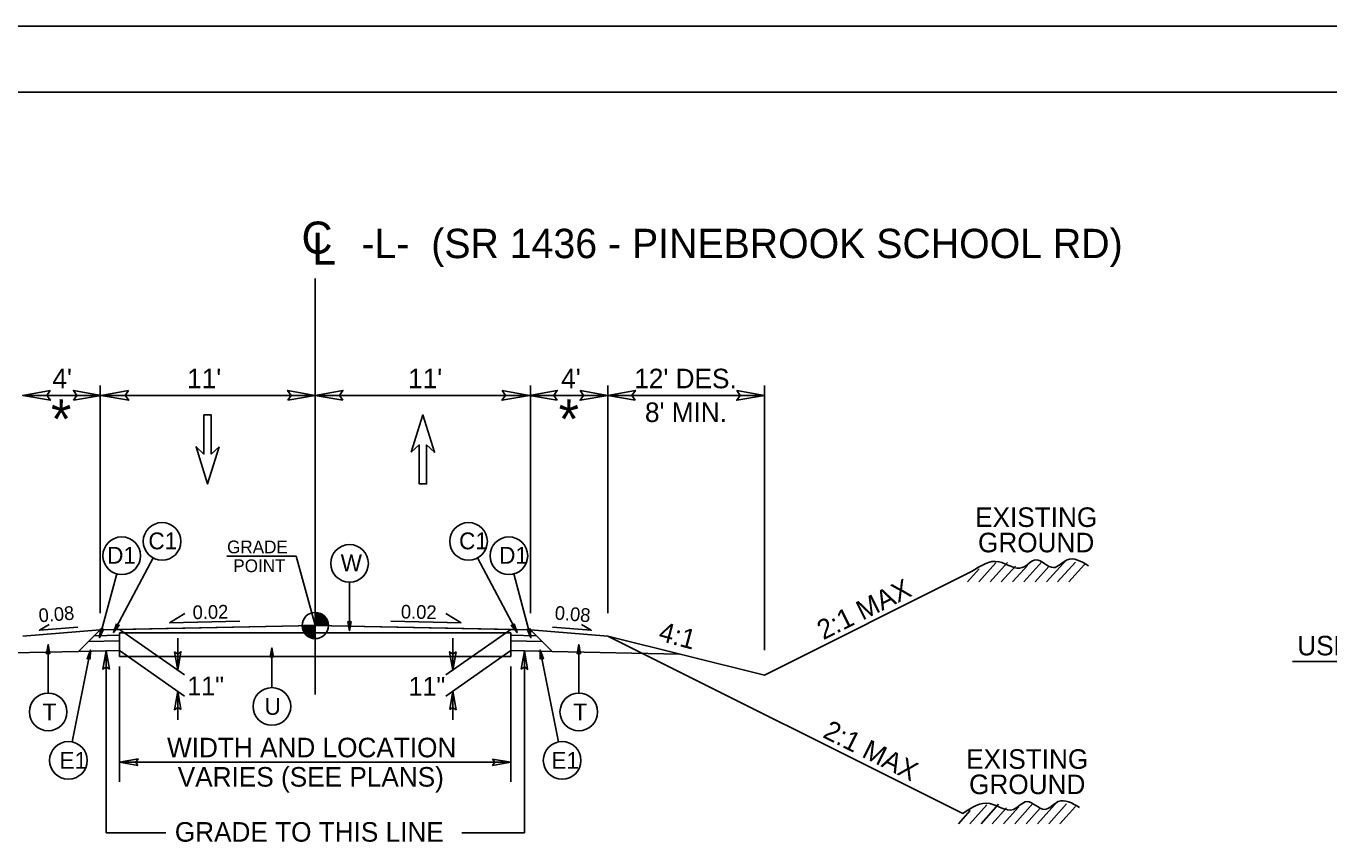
# Model space of a CAD drawing. Extents: x 1553884 to 1554215, y 810431 to 810779.
# Drawn here: x 1553946.8 to 1554013.4, y 810737.7 to 810779.4 of the extents above; entities that cross this region are included whole.
import ezdxf

# ---------------------------------------------------------------- set-up
doc = ezdxf.new("R2010")
doc.units = 0
for name, color, linetype in [('Old_Level_15', 7, 'Continuous'), ('Old_Level_2', 7, 'Continuous'), ('Old_Level_20', 7, 'Continuous'), ('Prop Hatching', 7, 'Continuous'), ('Prop Lane Arrow CELL', 7, 'Continuous'), ('Prop Shade Light', 7, 'Continuous'), ('Prop Terminator CELL', 7, 'Continuous'), ('Sheet Data Field CELL', 7, 'Continuous'), ('Sheet Sticker Exception Certification CELL', 7, 'Continuous'), ('Typical Arrow Superelevation CELL', 7, 'Continuous'), ('Typical Detail Pavement Repair CELL', 7, 'Continuous'), ('Typical Shoulder Slope CELL', 7, 'Continuous'), ('Typical Text Centerline CELL', 7, 'Continuous'), ('Typical Text ID Circle CELL', 7, 'Continuous')]:
    doc.layers.add(name, color=color, linetype=linetype)

msp = doc.modelspace()

# ---------------------------------------------------------------- linework, layer by layer
at = {"layer": 'Old_Level_15'}
for points in [[(1553948.075, 810760.787), (1553946.669, 810760.545), (1553948.083, 810760.295), (1553947.904, 810760.545)], [(1553949.263, 810760.303), (1553950.669, 810760.545), (1553949.256, 810760.795), (1553949.435, 810760.545)], [(1553952.075, 810760.787), (1553950.669, 810760.545), (1553952.083, 810760.295), (1553951.904, 810760.545)], [(1553960.212, 810760.303), (1553961.618, 810760.545), (1553960.204, 810760.795), (1553960.384, 810760.545)], [(1553963.024, 810760.303), (1553961.618, 810760.545), (1553963.032, 810760.795), (1553962.852, 810760.545)], [(1553971.16, 810760.787), (1553972.566, 810760.545), (1553971.152, 810760.295), (1553971.332, 810760.545)], [(1553973.972, 810760.303), (1553972.566, 810760.545), (1553973.98, 810760.795), (1553973.8, 810760.545)], [(1553975.16, 810760.787), (1553976.566, 810760.545), (1553975.152, 810760.295), (1553975.332, 810760.545)], [(1553977.972, 810760.303), (1553976.566, 810760.545), (1553977.98, 810760.795), (1553977.8, 810760.545)], [(1553983.16, 810760.787), (1553984.566, 810760.545), (1553983.152, 810760.295), (1553983.332, 810760.545)], [(1553950.638, 810748.627), (1553950.594, 810748.153), (1553950.798, 810748.587), (1553950.701, 810748.551)], [(1553951.455, 810748.869), (1553951.306, 810748.417), (1553951.601, 810748.794), (1553951.499, 810748.78)], [(1553963.45, 810748.978), (1553963.369, 810748.509), (1553963.286, 810748.98), (1553963.369, 810748.92)], [(1553971.781, 810748.869), (1553971.93, 810748.417), (1553971.635, 810748.794), (1553971.737, 810748.78)], [(1553972.597, 810748.627), (1553972.641, 810748.153), (1553972.438, 810748.587), (1553972.534, 810748.551)], [(1553948.049, 810747.337), (1553947.968, 810747.805), (1553947.885, 810747.334), (1553947.968, 810747.394)], [(1553950.119, 810747.051), (1553950.132, 810747.526), (1553949.957, 810747.08), (1553950.051, 810747.123)], [(1553951.096, 810746.544), (1553950.935, 810747.481), (1553950.768, 810746.539), (1553950.935, 810746.658)], [(1553954.426, 810747.436), (1553954.587, 810746.499), (1553954.754, 810747.441), (1553954.587, 810747.321)], [(1553959.482, 810747.168), (1553959.401, 810747.637), (1553959.318, 810747.166), (1553959.401, 810747.226)], [(1553968.81, 810747.436), (1553968.648, 810746.499), (1553968.482, 810747.441), (1553968.648, 810747.321)], [(1553972.14, 810746.544), (1553972.301, 810747.481), (1553972.468, 810746.539), (1553972.301, 810746.658)], [(1553973.117, 810747.051), (1553973.104, 810747.526), (1553973.278, 810747.08), (1553973.185, 810747.123)], [(1553975.166, 810747.337), (1553975.085, 810747.805), (1553975.002, 810747.334), (1553975.085, 810747.394)], [(1553954.749, 810744.479), (1553954.587, 810745.416), (1553954.421, 810744.474), (1553954.587, 810744.594)], [(1553968.487, 810744.479), (1553968.648, 810745.416), (1553968.815, 810744.474), (1553968.648, 810744.594)], [(1553952.555, 810741.63), (1553951.618, 810741.791), (1553952.56, 810741.958), (1553952.441, 810741.791)], [(1553970.681, 810741.953), (1553971.618, 810741.791), (1553970.675, 810741.625), (1553970.795, 810741.791)]]:
    msp.add_lwpolyline(points, close=True, dxfattribs=at)
at = {"layer": 'Old_Level_2'}
msp.add_line((1554154.325, 810776.052), (1553906.825, 810776.052), dxfattribs=at)
at = {"layer": 'Old_Level_20'}
for p, q in [((1553951.618, 810748.578), (1553954.94, 810746.251)), ((1553971.618, 810748.578), (1553968.295, 810746.251)), ((1553951.618, 810748.397), (1553971.618, 810748.397)), ((1553951.618, 810748.397), (1553951.618, 810747.189)), ((1553954.587, 810748.131), (1553954.587, 810746.499)), ((1553968.648, 810748.131), (1553968.648, 810746.499)), ((1553971.618, 810748.397), (1553971.618, 810747.189)), ((1553951.618, 810747.495), (1553954.94, 810745.169)), ((1553951.618, 810747.189), (1553971.618, 810747.189)), ((1553971.618, 810747.495), (1553968.295, 810745.169)), ((1553954.587, 810745.416), (1553954.587, 810743.955)), ((1553968.648, 810745.416), (1553968.648, 810743.955))]:
    msp.add_line(p, q, dxfattribs=at)
at = {"layer": 'Prop Hatching'}
msp.add_line((1553961.618, 810745.246), (1553961.618, 810766.512), dxfattribs=at)
for points in [[(1553956.711, 810757.92), (1553956.305, 810757.545), (1553956.305, 810759.545), (1553955.93, 810759.545), (1553955.93, 810757.545), (1553955.524, 810757.92), (1553956.118, 810756.014)], [(1553966.524, 810757.639), (1553966.93, 810758.014), (1553966.93, 810756.014), (1553967.305, 810756.014), (1553967.305, 810758.014), (1553967.711, 810757.639), (1553967.118, 810759.545)]]:
    msp.add_lwpolyline(points, close=True, dxfattribs=at)
at = {"layer": 'Prop Lane Arrow CELL'}
msp.add_line((1554156.35, 810779.427), (1553901.353, 810779.427), dxfattribs=at)
at = {"layer": 'Prop Shade Light'}
for p, q in [((1553950.618, 810748.558), (1553949.512, 810747.453)), ((1553961.618, 810748.778), (1553950.618, 810748.558)), ((1553961.618, 810748.778), (1553972.618, 810748.558)), ((1553972.618, 810748.558), (1553973.723, 810747.453)), ((1553951.618, 810747.995), (1553950.023, 810747.963)), ((1553951.618, 810748.283), (1553950.317, 810748.257)), ((1553971.618, 810748.283), (1553972.919, 810748.257)), ((1553971.618, 810747.995), (1553973.213, 810747.963)), ((1553951.618, 810747.495), (1553949.512, 810747.453)), ((1553971.618, 810747.495), (1553973.723, 810747.453))]:
    msp.add_line(p, q, dxfattribs=at)
for points in [[(1553950.317, 810748.257), (1553951.618, 810748.283), (1553951.618, 810748.283), (1553951.618, 810747.995), (1553950.023, 810747.963)], [(1553972.919, 810748.257), (1553971.618, 810748.283), (1553971.618, 810748.283), (1553971.618, 810747.995), (1553973.213, 810747.963)]]:
    msp.add_lwpolyline(points, close=True, dxfattribs=at)
at = {"layer": 'Prop Terminator CELL'}
msp.add_lwpolyline([(1553971.618, 810748.397), (1553951.618, 810748.397), (1553951.618, 810748.283), (1553950.317, 810748.257), (1553950.618, 810748.558), (1553951.618, 810748.578), (1553961.618, 810748.778), (1553971.618, 810748.578), (1553972.618, 810748.558), (1553972.919, 810748.257), (1553971.618, 810748.283)], close=True, dxfattribs=at)
at = {"layer": 'Sheet Data Field CELL'}
for p, q in [((1553961.618, 810748.778), (1553961.618, 810749.45)), ((1553960.946, 810748.778), (1553961.618, 810748.778)), ((1553961.616, 810748.107), (1553961.618, 810748.778)), ((1553961.618, 810748.778), (1553961.616, 810748.107)), ((1553962.289, 810748.778), (1553961.618, 810748.778))]:
    msp.add_line(p, q, dxfattribs=at)
for points in [[(1553961.624, 810749.45), (1553961.624, 810749.45), (1553961.624, 810748.778)], [(1553961.637, 810749.45), (1553961.637, 810748.778)], [(1553961.651, 810749.448), (1553961.651, 810748.778)], [(1553961.664, 810749.448), (1553961.664, 810748.778)], [(1553961.678, 810749.447), (1553961.678, 810748.778)], [(1553961.691, 810749.445), (1553961.691, 810748.778)], [(1553961.704, 810749.444), (1553961.704, 810748.778)], [(1553961.718, 810749.442), (1553961.718, 810748.778)], [(1553961.731, 810749.441), (1553961.731, 810748.778)], [(1553961.745, 810749.438), (1553961.745, 810748.778)], [(1553961.758, 810749.435), (1553961.758, 810748.778)], [(1553961.772, 810749.432), (1553961.772, 810748.778)], [(1553961.785, 810749.429), (1553961.785, 810748.778)], [(1553961.798, 810749.424), (1553961.798, 810748.778)], [(1553961.812, 810749.421), (1553961.812, 810748.778)], [(1553961.825, 810749.417), (1553961.825, 810748.778)], [(1553961.839, 810749.412), (1553961.839, 810748.778)], [(1553961.852, 810749.408), (1553961.852, 810748.778)], [(1553961.866, 810749.402), (1553961.866, 810748.778)], [(1553961.879, 810749.396), (1553961.879, 810748.778)], [(1553961.892, 810749.39), (1553961.892, 810748.778)], [(1553961.906, 810749.384), (1553961.906, 810748.778)], [(1553961.919, 810749.378), (1553961.919, 810748.778)], [(1553961.933, 810749.371), (1553961.933, 810748.778)], [(1553961.946, 810749.363), (1553961.946, 810748.778)], [(1553961.96, 810749.356), (1553961.96, 810748.778)], [(1553961.973, 810749.348), (1553961.973, 810748.778)], [(1553961.986, 810749.339), (1553961.986, 810748.778)], [(1553962, 810749.33), (1553962, 810748.778)], [(1553962.013, 810749.32), (1553962.013, 810748.778)], [(1553962.027, 810749.311), (1553962.027, 810748.778)], [(1553962.04, 810749.3), (1553962.04, 810748.778)], [(1553962.054, 810749.289), (1553962.054, 810748.778)], [(1553962.067, 810749.277), (1553962.067, 810748.778)], [(1553962.08, 810749.265), (1553962.08, 810748.778)], [(1553962.094, 810749.251), (1553962.094, 810748.778)], [(1553962.107, 810749.238), (1553962.107, 810748.778)], [(1553962.121, 810749.223), (1553962.121, 810748.778)], [(1553962.134, 810749.206), (1553962.134, 810748.778)], [(1553962.148, 810749.19), (1553962.148, 810748.778)], [(1553962.161, 810749.172), (1553962.161, 810748.778)], [(1553962.174, 810749.153), (1553962.174, 810748.778)], [(1553960.95, 810748.778), (1553960.95, 810748.705)], [(1553960.963, 810748.778), (1553960.963, 810748.626)], [(1553960.976, 810748.778), (1553960.976, 810748.578)], [(1553960.99, 810748.778), (1553960.99, 810748.538)], [(1553961.003, 810748.778), (1553961.003, 810748.507)], [(1553961.017, 810748.778), (1553961.017, 810748.478)], [(1553961.03, 810748.778), (1553961.03, 810748.453)], [(1553961.043, 810748.778), (1553961.043, 810748.429)], [(1553961.057, 810748.778), (1553961.057, 810748.408)], [(1553961.07, 810748.778), (1553961.07, 810748.389)], [(1553961.084, 810748.778), (1553961.084, 810748.371)], [(1553961.097, 810748.778), (1553961.097, 810748.355)], [(1553961.111, 810748.778), (1553961.111, 810748.338)], [(1553961.124, 810748.778), (1553961.124, 810748.323)], [(1553961.137, 810748.778), (1553961.137, 810748.308)], [(1553961.151, 810748.778), (1553961.151, 810748.295)], [(1553961.164, 810748.778), (1553961.164, 810748.283)], [(1553961.178, 810748.778), (1553961.178, 810748.271)], [(1553961.191, 810748.778), (1553961.191, 810748.259)], [(1553961.205, 810748.778), (1553961.205, 810748.249)], [(1553961.218, 810748.778), (1553961.218, 810748.238)], [(1553961.231, 810748.778), (1553961.231, 810748.229)], [(1553961.245, 810748.778), (1553961.245, 810748.22)], [(1553961.258, 810748.778), (1553961.258, 810748.211)], [(1553961.272, 810748.778), (1553961.272, 810748.202)], [(1553961.285, 810748.778), (1553961.285, 810748.195)], [(1553961.299, 810748.778), (1553961.299, 810748.187)], [(1553961.312, 810748.778), (1553961.312, 810748.18)], [(1553961.325, 810748.778), (1553961.325, 810748.174)], [(1553961.339, 810748.778), (1553961.339, 810748.168)], [(1553961.352, 810748.778), (1553961.352, 810748.162)], [(1553961.366, 810748.778), (1553961.366, 810748.156)], [(1553961.379, 810748.778), (1553961.379, 810748.15)], [(1553961.393, 810748.778), (1553961.393, 810748.146)], [(1553961.406, 810748.778), (1553961.406, 810748.141)], [(1553961.419, 810748.778), (1553961.419, 810748.137)], [(1553961.433, 810748.778), (1553961.433, 810748.134)], [(1553961.446, 810748.778), (1553961.446, 810748.129)], [(1553961.46, 810748.778), (1553961.46, 810748.126)], [(1553961.473, 810748.778), (1553961.473, 810748.123)], [(1553961.487, 810748.778), (1553961.487, 810748.12)], [(1553961.5, 810748.778), (1553961.5, 810748.117)], [(1553961.513, 810748.778), (1553961.513, 810748.116)], [(1553961.527, 810748.778), (1553961.527, 810748.113)], [(1553961.54, 810748.778), (1553961.54, 810748.111)], [(1553961.554, 810748.778), (1553961.554, 810748.11)], [(1553961.567, 810748.778), (1553961.567, 810748.108)], [(1553961.581, 810748.778), (1553961.581, 810748.108)], [(1553961.594, 810748.778), (1553961.594, 810748.107)], [(1553961.607, 810748.778), (1553961.607, 810748.107), (1553961.607, 810748.107)], [(1553962.188, 810749.132), (1553962.188, 810748.778)], [(1553962.201, 810749.11), (1553962.201, 810748.778)], [(1553962.215, 810749.086), (1553962.215, 810748.778)], [(1553962.228, 810749.057), (1553962.228, 810748.778)], [(1553962.242, 810749.026), (1553962.242, 810748.778)], [(1553962.255, 810748.989), (1553962.255, 810748.778)], [(1553962.268, 810748.942), (1553962.268, 810748.778)], [(1553962.282, 810748.874), (1553962.282, 810748.778)]]:
    msp.add_lwpolyline(points, dxfattribs=at)
msp.add_circle((1553961.617, 810748.778), 0.671, dxfattribs=at)
for start, end in [(359.99048, 89.99048), (179.99048, 269.99048)]:
    msp.add_arc((1553961.617, 810748.778), 0.671, start, end, dxfattribs=at)
at = {"layer": 'Typical Arrow Superelevation CELL'}
for p, q in [((1553954.164, 810748.922), (1553954.947, 810749.395)), ((1553969.072, 810748.922), (1553968.289, 810749.395)), ((1553954.164, 810748.922), (1553957.762, 810748.994)), ((1553969.072, 810748.922), (1553965.474, 810748.994)), ((1553950.935, 810738.184), (1553950.935, 810747.481)), ((1553972.301, 810738.184), (1553972.301, 810747.481)), ((1554011.552, 810746.931), (1554041.51, 810746.931)), ((1553953.98, 810738.184), (1553950.935, 810738.184)), ((1553969.107, 810738.184), (1553972.301, 810738.184))]:
    msp.add_line(p, q, dxfattribs=at)
for points in [[(1553949.491, 810748.698), (1553947.518, 810748.54), (1553948.019, 810748.824)], [(1553973.745, 810748.698), (1553975.717, 810748.54), (1553975.217, 810748.824)]]:
    msp.add_lwpolyline(points, dxfattribs=at)
at = {"layer": 'Typical Shoulder Slope CELL'}
for p, q in [((1553950.669, 810760.545), (1553946.669, 810760.545)), ((1553950.618, 810749.404), (1553950.618, 810761.045)), ((1553961.618, 810760.545), (1553950.669, 810760.545)), ((1553961.618, 810760.545), (1553972.566, 810760.545)), ((1553972.566, 810760.545), (1553976.566, 810760.545)), ((1553972.618, 810749.404), (1553972.618, 810761.045)), ((1553976.566, 810749.404), (1553976.566, 810761.045)), ((1553976.566, 810760.545), (1553984.566, 810760.545)), ((1553984.566, 810747.519), (1553984.566, 810761.045)), ((1553996.396, 810751.981), (1553995.521, 810751.009)), ((1553996.991, 810752.003), (1553996.097, 810751.009)), ((1553997.401, 810751.818), (1553996.673, 810751.009)), ((1553998.025, 810751.871), (1553997.249, 810751.009)), ((1553998.75, 810752.037), (1553997.825, 810751.009)), ((1553999.998, 810752.144), (1553998.977, 810751.009)), ((1554000.464, 810752.021), (1553999.553, 810751.009)), ((1554000.926, 810751.895), (1554000.129, 810751.009)), ((1553995.159, 810751.539), (1553984.566, 810746.242)), ((1553995.546, 810751.677), (1553994.945, 810751.009)), ((1553999.111, 810751.798), (1553998.401, 810751.009)), ((1553950.618, 810748.558), (1553946.669, 810748.242)), ((1553972.618, 810748.558), (1553976.566, 810748.242)), ((1553984.566, 810746.242), (1553976.566, 810748.242)), ((1553976.566, 810748.242), (1553994.702, 810739.175)), ((1553949.512, 810747.453), (1553942.989, 810747.322)), ((1553973.723, 810747.453), (1553980.246, 810747.322)), ((1553951.618, 810740.791), (1553951.618, 810746.689)), ((1553971.618, 810740.791), (1553971.618, 810746.689)), ((1553971.618, 810741.791), (1553951.618, 810741.791)), ((1553995.089, 810739.313), (1553994.488, 810738.644)), ((1553995.938, 810739.617), (1553995.064, 810738.644)), ((1553996.533, 810739.638), (1553995.64, 810738.644)), ((1553996.944, 810739.454), (1553996.216, 810738.644)), ((1553997.567, 810739.507), (1553996.792, 810738.644)), ((1553998.292, 810739.673), (1553997.368, 810738.644)), ((1553998.653, 810739.433), (1553997.944, 810738.644)), ((1553999.541, 810739.78), (1553998.52, 810738.644)), ((1554000.006, 810739.657), (1553999.096, 810738.644)), ((1554000.469, 810739.531), (1553999.672, 810738.644))]:
    msp.add_line(p, q, dxfattribs=at)
for points in [[(1553995.159, 810751.539), (1553996.554, 810752.038), (1553997.749, 810751.738), (1553998.446, 810752.137), (1553999.342, 810751.738), (1554000.039, 810752.137), (1554001.135, 810751.838)], [(1553994.702, 810739.175), (1553996.096, 810739.673), (1553997.291, 810739.374), (1553997.988, 810739.773), (1553998.885, 810739.374), (1553999.582, 810739.773), (1554000.677, 810739.474)]]:
    msp.add_spline(points, degree=3, dxfattribs=at)
at = {"layer": 'Typical Text Centerline CELL'}
msp.add_lwpolyline([(1553957.099, 810752.322), (1553960.637, 810752.322), (1553961.604, 810748.798)], dxfattribs=at)
at = {"layer": 'Typical Text ID Circle CELL'}
for p, q in [((1553953.335, 810752.232), (1553951.306, 810748.417)), ((1553969.901, 810752.232), (1553971.93, 810748.417)), ((1553951.475, 810751.418), (1553950.594, 810748.153)), ((1553971.761, 810751.418), (1553972.641, 810748.153)), ((1553963.369, 810750.994), (1553963.369, 810748.509)), ((1553947.968, 810745.32), (1553947.968, 810747.805)), ((1553949.191, 810742.826), (1553950.132, 810747.526)), ((1553959.401, 810745.603), (1553959.401, 810747.637)), ((1553974.044, 810742.826), (1553973.104, 810747.526)), ((1553975.085, 810745.32), (1553975.085, 810747.805))]:
    msp.add_line(p, q, dxfattribs=at)
for centre in [(1553953.786, 810753.081), (1553969.449, 810753.081), (1553951.725, 810752.346), (1553971.51, 810752.346), (1553963.369, 810751.956), (1553947.968, 810744.359), (1553959.401, 810744.641), (1553975.085, 810744.359), (1553949.003, 810741.883), (1553974.233, 810741.883)]:
    msp.add_circle(centre, 0.962, dxfattribs=at)

# ---------------------------------------------------------------- texts
at = {"layer": 'Old_Level_20'}
for p in [(1553955.079, 810745.214), (1553966.385, 810745.194)]:
    msp.add_text('11"', height=0.9558, dxfattribs=at).set_placement(p)
at = {"layer": 'Sheet Sticker Exception Certification CELL'}
for s, p in [('GRADE', (1553957.111, 810752.47)), ('POINT', (1553957.43, 810751.507))]:
    msp.add_text(s, height=0.6525, dxfattribs=at).set_placement(p)
at = {"layer": 'Typical Arrow Superelevation CELL'}
for s, height, p in [('-L-  (SR 1436 - PINEBROOK SCHOOL RD)', 1.5, (1553963.978, 810767.561)), ("4'", 1, (1553948.185, 810760.907)), ("11'", 1, (1553955.071, 810760.907)), ("11'", 1, (1553966.362, 810760.907)), ("4'", 1, (1553974.184, 810760.907)), ("12' DES.", 1, (1553977.919, 810760.907)), ('*', 2, (1553948.111, 810758.336)), ('*', 2, (1553974.054, 810758.336)), ("8' MIN.", 1, (1553978.464, 810759.183)), ('EXISTING', 1, (1553995.335, 810753.817)), ('GROUND', 1, (1553995.484, 810752.522)), ('USE TYPICAL SECTION NO. 1 AS FOLLOWS:', 1, (1554011.799, 810747.251)), ('WIDTH AND LOCATION', 1, (1553954.042, 810742.041)), ('EXISTING', 1, (1553994.877, 810741.452)), ('VARIES (SEE PLANS)', 1, (1553954.59, 810740.541)), ('GROUND', 1, (1553995.027, 810740.158)), ('GRADE TO THIS LINE', 1, (1553954.439, 810737.727))]:
    msp.add_text(s, height=height, dxfattribs=at).set_placement(p)
for s, height, rotation, p in [('2:1 MAX', 1, 26.56505, (1553987.583, 810748.024)), ('0.02', 0.7, 1.14587, (1553955.357, 810749.102)), ('0.02', 0.7, 358.85413, (1553965.988, 810749.14)), ('0.08', 0.7, 4.57392, (1553947.508, 810748.937)), ('0.08', 0.7, 355.42608, (1553973.834, 810749.088)), ('4:1', 1, 345.05299, (1553979.104, 810748.022)), ('2:1 MAX', 1, 333.43495, (1553987.498, 810743.086))]:
    msp.add_text(s, height=height, rotation=rotation, dxfattribs=at).set_placement(p)
at = {"layer": 'Typical Detail Pavement Repair CELL'}
for s, height, p in [('C1', 0.8608, (1553953.09, 810752.675)), ('C1', 0.8608, (1553968.967, 810752.675)), ('D1', 0.8608, (1553950.981, 810751.94)), ('D1', 0.8608, (1553971.015, 810751.94)), ('W', 0.861, (1553962.917, 810751.549)), ('T', 0.861, (1553947.685, 810743.928)), ('U', 0.861, (1553959.026, 810744.211)), ('T', 0.861, (1553974.802, 810743.928)), ('E1', 0.8608, (1553948.546, 810741.453)), ('E1', 0.8608, (1553973.684, 810741.453))]:
    msp.add_text(s, height=height, dxfattribs=at).set_placement(p)
at = {"layer": 'Typical Text Centerline CELL'}
msp.add_text('C', height=1.64, dxfattribs=at).set_placement((1553960.915, 810767.79))
msp.add_text('L', height=1.641, rotation=359.9469, dxfattribs=at).set_placement((1553961.461, 810767.23))

doc.saveas('drawing.dxf')
